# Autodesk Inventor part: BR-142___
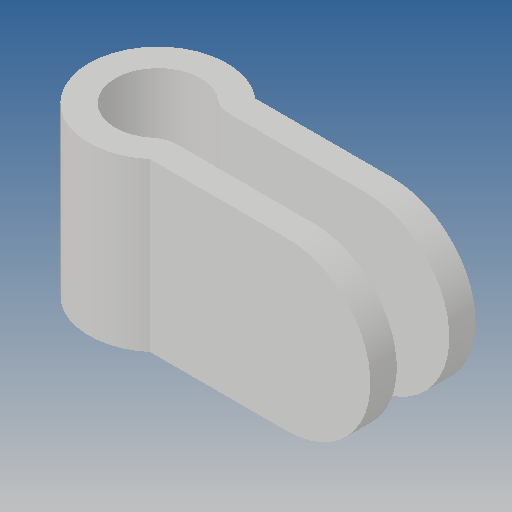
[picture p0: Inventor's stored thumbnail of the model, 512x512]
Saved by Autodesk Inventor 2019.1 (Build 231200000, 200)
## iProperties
Created: 2010-06
Part Number: BR-142___
Material: Ogólny
Document SubType Name: Modeling
Designer: CADENGINEERING4
Density: 1 g/cm^3
Appearance: Domyślna
Author: CADENGINEERING4
Revision Number: ANY
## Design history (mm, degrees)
feature "NONE"
node "Bryła1"
